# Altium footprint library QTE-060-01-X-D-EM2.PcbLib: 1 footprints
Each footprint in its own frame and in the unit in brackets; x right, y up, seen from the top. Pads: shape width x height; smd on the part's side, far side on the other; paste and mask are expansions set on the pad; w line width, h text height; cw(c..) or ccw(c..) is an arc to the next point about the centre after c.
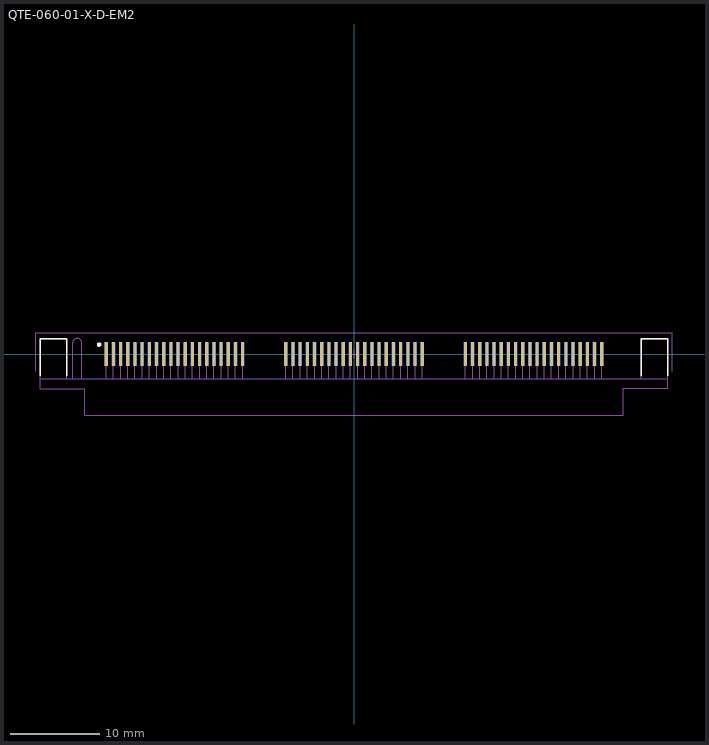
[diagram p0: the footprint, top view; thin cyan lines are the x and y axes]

## QTE-060-01-X-D-EM2 [mm] "0.80mm pitch, 120 pin, high speed terminal strip; w/edge mounts"
height 2.99
pads (120):
  rect 0.35x2.65 smd mask+0: 1(-27.603,0) 3(-26.803,0) 5(-26.003,0) 7(-25.203,0) 9(-24.403,0) 11(-23.603,0) 13(-22.803,0) 15(-22.003,0) 17(-21.203,0) 19(-20.403,0) 21(-19.603,0) 23(-18.803,0) 25(-18.003,0) 27(-17.203,0) 29(-16.403,0) 31(-15.603,0) 33(-14.803,0) 35(-14.003,0) 37(-13.203,0) 39(-12.403,0) 41(-7.6,0) 43(-6.8,0) 45(-6,0) 47(-5.2,0) 49(-4.4,0) 51(-3.6,0) 53(-2.8,0) 55(-2,0) 57(-1.2,0) 59(-0.4,0) 61(0.4,0) 63(1.2,0) 65(2,0) 67(2.8,0) 69(3.6,0) 71(4.4,0) 73(5.2,0) 75(6,0) 77(6.8,0) 79(7.6,0) 81(12.403,0) 83(13.203,0) 85(14.003,0) 87(14.803,0) 89(15.603,0) 91(16.403,0) 93(17.203,0) 95(18.003,0) 97(18.803,0) 99(19.603,0) 101(20.403,0) 103(21.203,0) 105(22.003,0) 107(22.803,0) 109(23.603,0) 111(24.403,0) 113(25.203,0) 115(26.003,0) 117(26.803,0) 119(27.603,0)
  rect 0.35x2.65 smd far side mask+0: 2(-27.603,0) 4(-26.803,0) 6(-26.003,0) 8(-25.203,0) 10(-24.403,0) 12(-23.603,0) 14(-22.803,0) 16(-22.003,0) 18(-21.203,0) 20(-20.403,0) 22(-19.603,0) 24(-18.803,0) 26(-18.003,0) 28(-17.203,0) 30(-16.403,0) 32(-15.603,0) 34(-14.803,0) 36(-14.003,0) 38(-13.203,0) 40(-12.403,0) 42(-7.6,0) 44(-6.8,0) 46(-6,0) 48(-5.2,0) 50(-4.4,0) 52(-3.6,0) 54(-2.8,0) 56(-2,0) 58(-1.2,0) 60(-0.4,0) 62(0.4,0) 64(1.2,0) 66(2,0) 68(2.8,0) 70(3.6,0) 72(4.4,0) 74(5.2,0) 76(6,0) 78(6.8,0) 80(7.6,0) 82(12.403,0) 84(13.203,0) 86(14.003,0) 88(14.803,0) 90(15.603,0) 92(16.403,0) 94(17.203,0) 96(18.003,0) 98(18.803,0) 100(19.603,0) 102(20.403,0) 104(21.203,0) 106(22.003,0) 108(22.803,0) 110(23.603,0) 112(24.403,0) 114(25.203,0) 116(26.003,0) 118(26.803,0) 120(27.603,0)
Top Overlay:
  circle w0.25: c-28.4,1.05 r0.125
  lines w0.2: -34.95,-2.4 -34.95,1.7 -32,1.7 -32,-2.4 ; 32,-2.4 32,1.7 34.95,1.7 34.95,-2.4
Top Solder:
  lines w0.127: -27.603,0 -27.603,1.333 ; -26.803,0 -26.803,1.333 ; -26.003,0 -26.003,1.333 ; -25.203,0 -25.203,1.333 ; -24.403,0 -24.403,1.333 ; -23.603,0 -23.603,1.333 ; -22.803,0 -22.803,1.333 ; -22.003,0 -22.003,1.333 ; -21.203,0 -21.203,1.333 ; -20.403,0 -20.403,1.333 ; -19.603,0 -19.603,1.333 ; -18.803,0 -18.803,1.333 ; -18.003,0 -18.003,1.333 ; -17.203,0 -17.203,1.333 ; -16.403,0 -16.403,1.333 ; -15.603,0 -15.603,1.333 ; -14.803,0 -14.803,1.333 ; -14.003,0 -14.003,1.333 ; -13.203,0 -13.203,1.333 ; -12.403,0 -12.403,1.333 ; -7.6,0 -7.6,1.333 ; -6.8,0 -6.8,1.333 ; -6,0 -6,1.333 ; -5.2,0 -5.2,1.333 ; -4.4,0 -4.4,1.333 ; -3.6,0 -3.6,1.333 ; -2.8,0 -2.8,1.333 ; -2,0 -2,1.333 ; -1.2,0 -1.2,1.333 ; -0.4,0 -0.4,1.333 ; 0.4,0 0.4,1.333 ; 1.2,0 1.2,1.333 ; 2,0 2,1.333 ; 2.8,0 2.8,1.333 ; 3.6,0 3.6,1.333 ; 4.4,0 4.4,1.333 ; 5.2,0 5.2,1.333 ; 6,0 6,1.333 ; 6.8,0 6.8,1.333 ; 7.6,0 7.6,1.333 ; 12.403,0 12.403,1.333 ; 13.203,0 13.203,1.333 ; 14.003,0 14.003,1.333 ; 14.803,0 14.803,1.333 ; 15.603,0 15.603,1.333 ; 16.403,0 16.403,1.333 ; 17.203,0 17.203,1.333 ; 18.003,0 18.003,1.333 ; 18.803,0 18.803,1.333 ; 19.603,0 19.603,1.333 ; 20.403,0 20.403,1.333 ; 21.203,0 21.203,1.333 ; 22.003,0 22.003,1.333 ; 22.803,0 22.803,1.333 ; 23.603,0 23.603,1.333 ; 24.403,0 24.403,1.333 ; 25.203,0 25.203,1.333 ; 26.003,0 26.003,1.333 ; 26.803,0 26.803,1.333 ; 27.603,0 27.603,1.333
Bottom Solder:
  lines w0.127: -27.603,0 -27.603,1.333 ; -26.803,0 -26.803,1.333 ; -26.003,0 -26.003,1.333 ; -25.203,0 -25.203,1.333 ; -24.403,0 -24.403,1.333 ; -23.603,0 -23.603,1.333 ; -22.803,0 -22.803,1.333 ; -22.003,0 -22.003,1.333 ; -21.203,0 -21.203,1.333 ; -20.403,0 -20.403,1.333 ; -19.603,0 -19.603,1.333 ; -18.803,0 -18.803,1.333 ; -18.003,0 -18.003,1.333 ; -17.203,0 -17.203,1.333 ; -16.403,0 -16.403,1.333 ; -15.603,0 -15.603,1.333 ; -14.803,0 -14.803,1.333 ; -14.003,0 -14.003,1.333 ; -13.203,0 -13.203,1.333 ; -12.403,0 -12.403,1.333 ; -7.6,0 -7.6,1.333 ; -6.8,0 -6.8,1.333 ; -6,0 -6,1.333 ; -5.2,0 -5.2,1.333 ; -4.4,0 -4.4,1.333 ; -3.6,0 -3.6,1.333 ; -2.8,0 -2.8,1.333 ; -2,0 -2,1.333 ; -1.2,0 -1.2,1.333 ; -0.4,0 -0.4,1.333 ; 0.4,0 0.4,1.333 ; 1.2,0 1.2,1.333 ; 2,0 2,1.333 ; 2.8,0 2.8,1.333 ; 3.6,0 3.6,1.333 ; 4.4,0 4.4,1.333 ; 5.2,0 5.2,1.333 ; 6,0 6,1.333 ; 6.8,0 6.8,1.333 ; 7.6,0 7.6,1.333 ; 12.403,0 12.403,1.333 ; 13.203,0 13.203,1.333 ; 14.003,0 14.003,1.333 ; 14.803,0 14.803,1.333 ; 15.603,0 15.603,1.333 ; 16.403,0 16.403,1.333 ; 17.203,0 17.203,1.333 ; 18.003,0 18.003,1.333 ; 18.803,0 18.803,1.333 ; 19.603,0 19.603,1.333 ; 20.403,0 20.403,1.333 ; 21.203,0 21.203,1.333 ; 22.003,0 22.003,1.333 ; 22.803,0 22.803,1.333 ; 23.603,0 23.603,1.333 ; 24.403,0 24.403,1.333 ; 25.203,0 25.203,1.333 ; 26.003,0 26.003,1.333 ; 26.803,0 26.803,1.333 ; 27.603,0 27.603,1.333
Mechanical 13:
  lines w0.1: -32.003,-2.75 -32.003,1.7 -34.95,1.7 -34.95,-2.75 ; -31.351,-2.75 -31.351,1.242 cw(c-30.843,1.242) -30.335,1.242 -30.335,-2.75 ; -27.603,-2.75 -27.603,0 ; -26.803,-2.75 -26.803,0 ; -26.003,-2.75 -26.003,0 ; -25.203,-2.75 -25.203,0 ; -24.403,-2.75 -24.403,0 ; -23.603,-2.75 -23.603,0 ; -22.803,-2.75 -22.803,0 ; -22.003,-2.75 -22.003,0 ; -21.203,-2.75 -21.203,0 ; -20.403,-2.75 -20.403,0 ; -19.603,-2.75 -19.603,0 ; -18.803,-2.75 -18.803,0 ; -18.003,-2.75 -18.003,0 ; -17.203,-2.75 -17.203,0 ; -16.403,-2.75 -16.403,0 ; -15.603,-2.75 -15.603,0 ; -14.803,-2.75 -14.803,0 ; -14.003,-2.75 -14.003,0 ; -13.203,-2.75 -13.203,0 ; -12.403,-2.75 -12.403,0 ; -7.6,-2.75 -7.6,0 ; -6.8,-2.75 -6.8,0 ; -6,-2.75 -6,0 ; -5.2,-2.75 -5.2,0 ; -4.4,-2.75 -4.4,0 ; -3.6,-2.75 -3.6,0 ; -2.8,-2.75 -2.8,0 ; -2,-2.75 -2,0 ; -1.2,-2.75 -1.2,0 ; -0.4,-2.75 -0.4,0 ; 0.4,-2.75 0.4,0 ; 1.2,-2.75 1.2,0 ; 2,-2.75 2,0 ; 2.8,-2.75 2.8,0 ; 3.6,-2.75 3.6,0 ; 4.4,-2.75 4.4,0 ; 5.2,-2.75 5.2,0 ; 6,-2.75 6,0 ; 6.8,-2.75 6.8,0 ; 7.6,-2.75 7.6,0 ; 12.403,-2.75 12.403,0 ; 13.203,-2.75 13.203,0 ; 14.003,-2.75 14.003,0 ; 14.803,-2.75 14.803,0 ; 15.603,-2.75 15.603,0 ; 16.403,-2.75 16.403,0 ; 17.203,-2.75 17.203,0 ; 18.003,-2.75 18.003,0 ; 18.803,-2.75 18.803,0 ; 19.603,-2.75 19.603,0 ; 20.403,-2.75 20.403,0 ; 21.203,-2.75 21.203,0 ; 22.003,-2.75 22.003,0 ; 22.803,-2.75 22.803,0 ; 23.603,-2.75 23.603,0 ; 24.403,-2.75 24.403,0 ; 25.203,-2.75 25.203,0 ; 26.003,-2.75 26.003,0 ; 26.803,-2.75 26.803,0 ; 27.603,-2.75 27.603,0 ; 32,-2.75 32,1.7 34.95,1.7 34.95,-2.75 ; -34.95,-2.75 34.95,-2.75 ; -34.95,-2.75 -34.95,-3.85 -30.004,-3.85 -30.004,-6.79 30.004,-6.79 30.004,-3.83 34.95,-3.83 34.95,-2.75
  text ".Designator" at 0,0 h1.52
Mechanical 15:
  lines w0.05: -35.45,-1.895 -35.45,2.35 35.45,2.35 35.45,-1.895 ; -0.5,0 0.5,0 ; 0,-0.5 0,0.5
